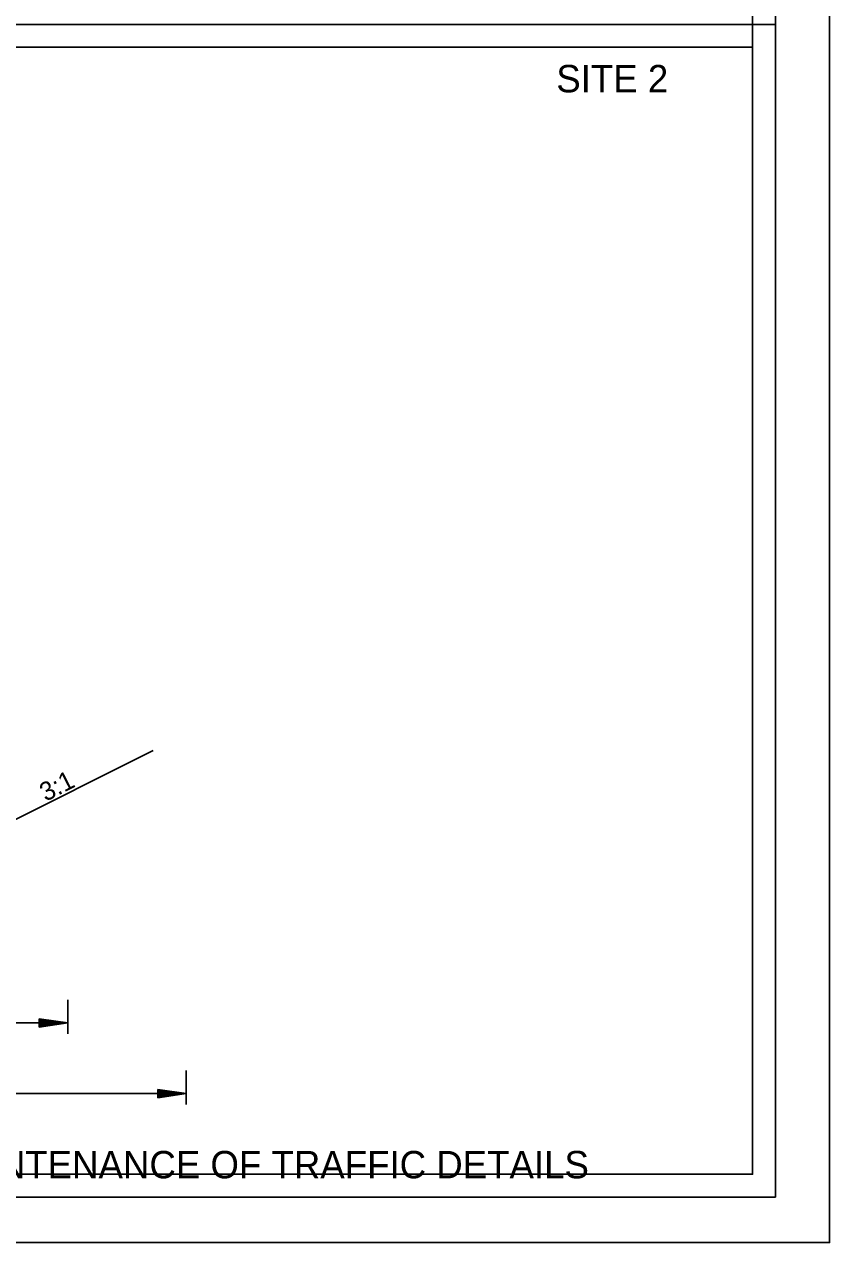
# Model space of a CAD drawing. Extents: x 1368648 to 1927880, y -1037443 to 380209.
# Drawn here: x 1373059 to 1373412, y 378686 to 379220 of the extents above; entities that cross this region are included whole.
import ezdxf

# ---------------------------------------------------------------- set-up
doc = ezdxf.new("R2010")
doc.units = 0
for name, color, linetype in [('R_Border', 7, 'Continuous'), ('R_Border Title', 7, 'Continuous'), ('R_Dimension', 7, 'Continuous'), ('R_Fin Surface', 7, 'Continuous'), ('R_No Plot', 7, 'Continuous'), ('R_Xsect Slope', 7, 'Continuous')]:
    doc.layers.add(name, color=color, linetype=linetype)

msp = doc.modelspace()

# ---------------------------------------------------------------- linework, layer by layer
at = {"layer": 'R_Border'}
for p, q in [((1373388.3, 378705.96), (1373388.3, 379733.26)), ((1373388.3, 379219.61), (1371807.4, 379219.61)), ((1373388.3, 378705.96), (1371807.4, 378705.96))]:
    msp.add_line(p, q, dxfattribs=at)
at = {"layer": 'R_Dimension'}
for p, q in [((1373078.23, 378792.37), (1373078.23, 378779.9)), ((1373065.73, 378784.12), (1373078.23, 378782.24)), ((1373065.73, 378780.37), (1373065.73, 378784.12)), ((1373065.73, 378783.8), (1373076.15, 378782.24)), ((1373065.73, 378783.49), (1373074, 378782.24)), ((1373065.73, 378783.17), (1373071.92, 378782.24)), ((1373078.23, 378782.24), (1372709.49, 378782.24)), ((1373065.73, 378782.85), (1373069.8, 378782.24)), ((1373065.73, 378782.54), (1373067.71, 378782.24)), ((1373065.73, 378780.37), (1373078.23, 378782.24)), ((1373065.73, 378781.64), (1373069.8, 378782.24)), ((1373065.73, 378781), (1373074, 378782.24)), ((1373065.73, 378780.68), (1373076.15, 378782.24)), ((1373065.73, 378781.31), (1373071.92, 378782.24)), ((1373065.73, 378781.95), (1373067.71, 378782.24)), ((1373078.23, 378779.9), (1373078.23, 378777.44)), ((1373130.18, 378761.43), (1373130.18, 378748.96)), ((1373130.18, 378751.3), (1372656.97, 378751.3)), ((1373117.68, 378753.18), (1373130.18, 378751.3)), ((1373117.68, 378749.43), (1373117.68, 378753.18)), ((1373117.68, 378752.86), (1373128.1, 378751.3)), ((1373117.68, 378752.54), (1373125.95, 378751.3)), ((1373117.68, 378752.23), (1373123.86, 378751.3)), ((1373117.68, 378751.91), (1373121.75, 378751.3)), ((1373117.68, 378751.59), (1373119.66, 378751.3)), ((1373117.68, 378749.43), (1373130.18, 378751.3)), ((1373117.68, 378750.69), (1373121.75, 378751.3)), ((1373117.68, 378750.06), (1373125.95, 378751.3)), ((1373117.68, 378749.74), (1373128.1, 378751.3)), ((1373117.68, 378750.37), (1373123.86, 378751.3)), ((1373117.68, 378751.01), (1373119.66, 378751.3)), ((1373130.18, 378748.96), (1373130.18, 378746.5))]:
    msp.add_line(p, q, dxfattribs=at)
at = {"layer": 'R_Fin Surface'}
msp.add_line((1373115.72, 378901.63), (1373032.24, 378859.9), dxfattribs=at)
at = {"layer": 'R_No Plot'}
for points in [[(1371745.37, 379752.73), (1373412.07, 379752.73), (1373412.07, 378686.04), (1371745.37, 378686.04)], [(1371817.4, 379723.26), (1373065.1, 379723.26), (1373065.1, 379673.86), (1373152.8, 379673.86), (1373273.3, 379673.86), (1373273.3, 379562.19), (1373378.3, 379562.19), (1373378.3, 378715.96), (1371817.4, 378715.96)], [(1371817.4, 379209.61), (1373378.3, 379209.61), (1373378.3, 378715.96), (1371817.4, 378715.96)]]:
    msp.add_lwpolyline(points, close=True, dxfattribs=at)

# ---------------------------------------------------------------- texts
at = {"layer": 'R_Border Title'}
for s, p in [('SITE 2', (1373292.29, 379189.84)), ('MAINTENANCE OF TRAFFIC DETAILS', (1373019.5, 378714.2))]:
    msp.add_text(s, height=12, dxfattribs=at).set_placement(p)
at = {"layer": 'R_Xsect Slope'}
msp.add_text('3:1', height=8.125, rotation=27.1112, dxfattribs=at).set_placement((1373068.56, 378879.05))

doc.saveas('drawing.dxf')
